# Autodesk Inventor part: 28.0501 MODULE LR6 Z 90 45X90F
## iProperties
Created: 2007-07
Part Number: 28.0501 MODULE LR6 Z 90 45X90F
Material: Aluminum-6061
Document SubType Name: Modeling
Designer: Andy Moles
Density: 2.71 g/cm^3
Author: Andy Moles
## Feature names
1. Extrusion1
